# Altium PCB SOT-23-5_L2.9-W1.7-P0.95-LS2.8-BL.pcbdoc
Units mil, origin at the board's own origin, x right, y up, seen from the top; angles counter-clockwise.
Board outline 631.02 x 641.74 mil, 2 copper layers (Top Layer, Bottom Layer), stack 0 mil thick; 1 components, 0 nets, 5 pads, 0 vias.
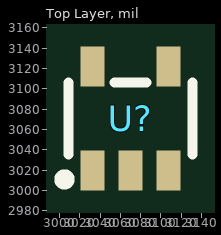
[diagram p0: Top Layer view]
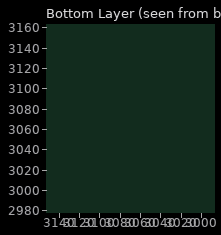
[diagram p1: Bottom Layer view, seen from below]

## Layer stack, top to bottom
Top Layer: signal copper (thickness not stored)
Bottom Layer: signal copper (thickness not stored)

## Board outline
3381.02,2750 2750,2750 2750,3391.74 3381.02,3391.74

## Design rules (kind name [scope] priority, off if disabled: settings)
PasteMaskExpansion "Paste Mask Expansion" [All] p1: expansion=0
SolderMaskExpansion "Solder Mask Expansion" [IsVia] p1: expansion=-1000 istentingtop=TRUE
SolderMaskExpansion "Solder Mask Expansion" [All] p2: expansion=2 istentingtop=FALSE

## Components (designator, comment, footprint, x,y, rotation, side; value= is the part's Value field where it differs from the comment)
U? "" SOT-23-5_L2.9-W1.7-P0.95-LS2.8-BL 3070,3070.87 r0 top

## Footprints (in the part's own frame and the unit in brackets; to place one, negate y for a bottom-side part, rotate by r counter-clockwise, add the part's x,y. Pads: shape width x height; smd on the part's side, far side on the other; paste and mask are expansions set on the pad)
SOT-23-5_L2.9-W1.7-P0.95-LS2.8-BL [mm]
  rect 0.6x1 smd: 1(-0.95,-1.3) 2(0,-1.3) 3(0.95,-1.3) 4(0.95,1.3) 5(-0.95,1.3)
  silkscreen extent -1.78,-1.65 1.55,0.9

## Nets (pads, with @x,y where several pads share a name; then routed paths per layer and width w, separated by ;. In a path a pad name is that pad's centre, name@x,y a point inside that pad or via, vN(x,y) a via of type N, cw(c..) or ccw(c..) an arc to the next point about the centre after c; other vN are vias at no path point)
pads on no net: U?.1 U?.2 U?.3 U?.4 U?.5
